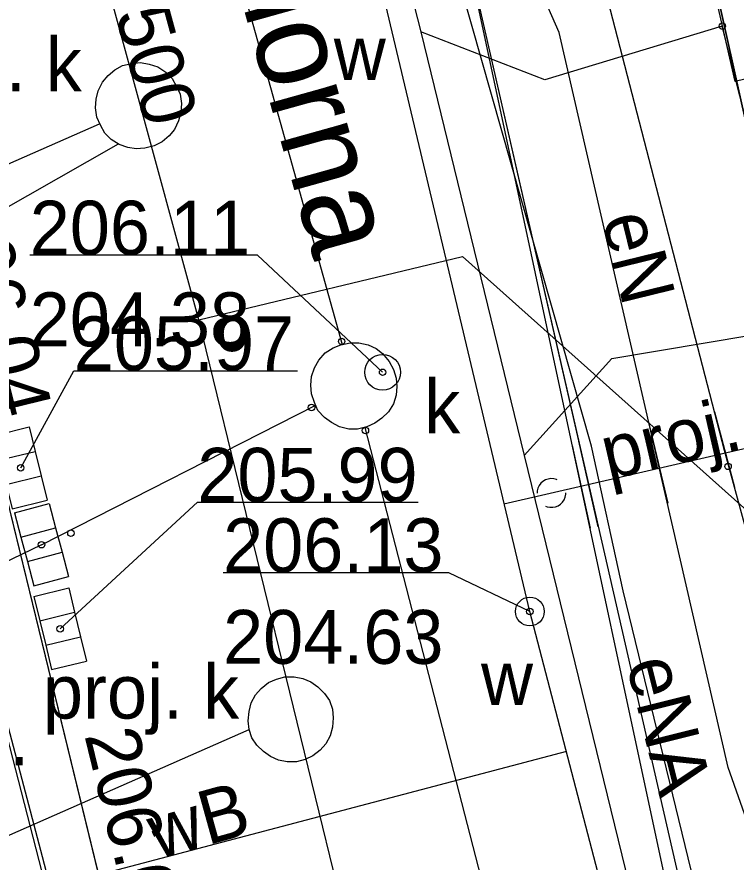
# Model space of a CAD drawing. Extents: x 6512400 to 6513200, y 6022500 to 6022750.
# Drawn here: x 6512855.79 to 6512865.8, y 6022590.23 to 6022602 of the extents above; entities that cross this region are included whole.
import ezdxf

# ---------------------------------------------------------------- set-up
doc = ezdxf.new("R2010")
doc.units = 0
for name, color, linetype in [('217-kontur klasyfikacyjny', 7, 'Continuous'), ('218-kontur użytku gruntowego', 7, 'Continuous'), ('219-działka ewidencyjna', 7, 'Continuous'), ('994-Nazwa ulicy', 7, 'Continuous'), ('budynek projektowany (powierzchnia)', 7, 'Continuous'), ('inna obudowa przewodu - sieć elektroenergetyczna (linia)', 7, 'Continuous'), ('jezdnia', 7, 'Continuous'), ('jezdnia (powierzchnia)', 7, 'Continuous'), ('jezdnia-Atr17', 7, 'Continuous'), ('komora podziemna - przewód kanalizacyjny (powierzchnia)', 7, 'Continuous'), ('kratka ściekowa', 7, 'Continuous'), ('krawężnik', 7, 'Continuous'), ('krawężnik (linia)', 7, 'Continuous'), ('obudowa przewodu projektowana lub w budowie (sieć elektroenergetyczna) - ob. projektowany', 7, 'Continuous'), ('obudowa przewodu projektowana lub w budowie (sieć gazowa) - ob. projektowany', 7, 'Continuous'), ('ogrodzenie trwałe (powierzchnia)', 7, 'Continuous'), ('pikieta sztuczna-Atr2', 7, 'Continuous'), ('przewód elektroenergetyczny (linia)', 7, 'Continuous'), ('przewód elektroenergetyczny (linia)-Atr1', 7, 'Continuous'), ('przewód gazowy (linia)', 7, 'Continuous'), ('przewód kanalizacyjny (linia)', 7, 'Continuous'), ('przewód kanalizacyjny (linia)-Atr1', 7, 'Continuous'), ('przewód kanalizacyjny - projektowany lub w budowie (linia) - ob. projektowany', 7, 'Continuous'), ('przewód wodociągowy (linia)', 7, 'Continuous'), ('przewód wodociągowy (linia)-Atr1', 7, 'Continuous'), ('przewód wodociągowy - projektowany lub w budowie (linia) - ob. projektowany', 7, 'Continuous'), ('przewód wodociągowy - projektowany lub w budowie (linia) - ob. projektowany-Atr1', 7, 'Continuous'), ('punkt o określonej wysokości (sieć gazowa)', 7, 'Continuous'), ('punkt o określonej wysokości (sieć kanalizacyjna)', 7, 'Continuous'), ('punkt o określonej wysokości (sieć kanalizacyjna)-Atr2', 7, 'Continuous'), ('punkt o określonej wysokości (sieć kanalizacyjna)-Atr3', 7, 'Continuous'), ('punkt o określonej wysokości (sieć wodociągowa)', 7, 'Continuous'), ('punkt o określonej wysokości (sieć wodociągowa)-Atr2', 7, 'Continuous'), ('punkt o określonej wysokości (sieć wodociągowa)-Atr3', 7, 'Continuous'), ('punkt wysokościowy naturalny', 7, 'Continuous'), ('rzedna', 7, 'Continuous'), ('rzedna-Atr2', 7, 'Continuous'), ('urządzenie techniczne projektowane lub w budowie (sieć kanalizacyjna) - powierzchnia - ob. projektowany', 7, 'Continuous'), ('urządzenie techniczne projektowane lub w budowie (sieć kanalizacyjna) - powierzchnia - ob. projektowany-Atr17', 7, 'Continuous'), ('urządzenie techniczne projektowane lub w budowie (sieć wodociągowa) - punkt - ob. projektowany', 7, 'Continuous'), ('właz okrągły - siec kanalizacyjna (punkt)', 7, 'Continuous'), ('właz okrągły - siec kanalizacyjna (punkt)-Atr17', 7, 'Continuous'), ('zasuwa - siec wodociągowa (punkt)', 7, 'Continuous'), ('zasuwa - siec wodociągowa (punkt)-Atr17', 7, 'Continuous')]:
    doc.layers.add(name, color=color, linetype=linetype)

# ---------------------------------------------------------------- blocks, each defined once
blk = doc.blocks.new('PW01')
blk.add_circle((0, 0), 0.045)
blk = doc.blocks.new('US22')
blk.add_circle((0, 0), 0.25)
blk = doc.blocks.new('US25')
blk.add_circle((0, 0), 0.2)
blk = doc.blocks.new('US01P')
for points in [[(0.082, 0.181), (0.072, 0.186), (0.034, 0.197), (-0.006, 0.2), (-0.046, 0.194), (-0.084, 0.182), (-0.118, 0.161), (-0.148, 0.135), (-0.172, 0.103), (-0.189, 0.066), (-0.198, 0.028), (-0.2, -0.001)], [(-0.082, -0.182), (-0.061, -0.191), (-0.022, -0.199), (0.018, -0.199), (0.057, -0.192), (0.094, -0.177), (0.127, -0.155), (0.155, -0.126), (0.177, -0.093), (0.192, -0.056), (0.199, -0.016), (0.2, 0)]]:
    blk.add_lwpolyline(points)
blk = doc.blocks.new('US05')
for p, q in [((-0.525, -0.25), (-0.525, 0.25)), ((-0.525, 0.25), (-0.175, 0.25)), ((-0.175, -0.25), (-0.175, 0.25)), ((-0.175, 0.25), (0.175, 0.25)), ((0.175, -0.25), (0.175, 0.25)), ((0.175, 0.25), (0.525, 0.25)), ((0.525, -0.25), (0.525, 0.25)), ((-0.525, -0.25), (-0.175, -0.25)), ((-0.175, -0.25), (0.175, -0.25)), ((0.175, -0.25), (0.525, -0.25))]:
    blk.add_line(p, q)

msp = doc.modelspace()

# ---------------------------------------------------------------- linework, layer by layer
at = {"layer": '217-kontur klasyfikacyjny'}
msp.add_lwpolyline([(6512862.63, 6022615.38), (6512866.69, 6022597.16)], dxfattribs=at)
at = {"layer": '218-kontur użytku gruntowego'}
for points in [[(6512862.63, 6022615.38), (6512866.69, 6022597.16)], [(6512866.69, 6022597.16), (6512862.63, 6022615.38)]]:
    msp.add_lwpolyline(points, dxfattribs=at)
at = {"layer": '219-działka ewidencyjna'}
msp.add_lwpolyline([(6512866.69, 6022597.16), (6512862.63, 6022615.38)], dxfattribs=at)
at = {"layer": 'budynek projektowany (powierzchnia)'}
msp.add_lwpolyline([(6512876.905, 6022604.629), (6512866.3, 6022602.19), (6512866.5, 6022601.27), (6512865.79, 6022601.1), (6512863.94, 6022609.18), (6512865.92, 6022609.63), (6512865.01, 6022613.81), (6512862.96, 6022613.3), (6512860.72, 6022623.09)], dxfattribs=at)
at = {"layer": 'inna obudowa przewodu - sieć elektroenergetyczna (linia)'}
msp.add_lwpolyline([(6512862.37, 6022601.52), (6512863.69, 6022595.73)], dxfattribs=at)
at = {"layer": 'jezdnia'}
msp.add_lwpolyline([(6512857.23, 6022588.82), (6512855.05, 6022597.75), (6512854.94, 6022596.77), (6512854.71, 6022596.06), (6512854.24, 6022595.41), (6512853.71, 6022594.99), (6512853.21, 6022594.73), (6512852.17, 6022594.41), (6512852.27, 6022594.15), (6512853.67, 6022590.44), (6512853.87, 6022590.02), (6512854.31, 6022590.11), (6512855.01, 6022590.11), (6512855.7, 6022590.01), (6512856.23, 6022589.8), (6512856.78, 6022589.31)], close=True, dxfattribs=at)
at = {"layer": 'jezdnia (powierzchnia)'}
msp.add_lwpolyline([(6512861.41, 6022601.79), (6512862.85, 6022595.89), (6512864.07, 6022597.24), (6512866.67, 6022597.68), (6512865.61, 6022601.87), (6512863.14, 6022601.12)], close=True, dxfattribs=at)
at = {"layer": 'komora podziemna - przewód kanalizacyjny (powierzchnia)'}
msp.add_lwpolyline([(6512861.08, 6022596.85), (6512861.07, 6022596.73), (6512861.03, 6022596.61), (6512860.96, 6022596.5), (6512860.87, 6022596.41), (6512860.77, 6022596.34), (6512860.66, 6022596.29), (6512860.53, 6022596.26), (6512860.41, 6022596.26), (6512860.28, 6022596.29), (6512860.17, 6022596.35), (6512860.07, 6022596.42), (6512859.98, 6022596.52), (6512859.93, 6022596.63), (6512859.89, 6022596.75), (6512859.88, 6022596.87), (6512859.89, 6022596.99), (6512859.93, 6022597.11), (6512859.99, 6022597.22), (6512860.08, 6022597.32), (6512860.19, 6022597.39), (6512860.3, 6022597.43), (6512860.43, 6022597.46), (6512860.55, 6022597.46), (6512860.68, 6022597.43), (6512860.79, 6022597.38), (6512860.88, 6022597.31), (6512860.97, 6022597.2), (6512861.03, 6022597.09), (6512861.07, 6022596.97)], close=True, dxfattribs=at)
at = {"layer": 'krawężnik'}
msp.add_lwpolyline([(6512857.23, 6022588.82), (6512855.05, 6022597.75), (6512854.94, 6022596.77), (6512854.71, 6022596.06), (6512854.24, 6022595.41), (6512853.71, 6022594.99), (6512853.21, 6022594.73), (6512852.17, 6022594.41), (6512852.27, 6022594.15), (6512853.67, 6022590.44), (6512853.87, 6022590.02), (6512854.31, 6022590.11), (6512855.01, 6022590.11), (6512855.7, 6022590.01), (6512856.23, 6022589.8), (6512856.78, 6022589.31)], close=True, dxfattribs=at)
at = {"layer": 'krawężnik (linia)'}
for points in [[(6512859.76, 6022608.23), (6512861.41, 6022601.79)], [(6512858.01, 6022586.22), (6512857.23, 6022588.81), (6512855.05, 6022597.75), (6512854.71, 6022599.38), (6512853.35, 6022605.1)], [(6512862.85, 6022595.89), (6512865.97, 6022583.13), (6512868.17, 6022574.3)]]:
    msp.add_lwpolyline(points, dxfattribs=at)
at = {"layer": 'obudowa przewodu projektowana lub w budowie (sieć elektroenergetyczna) - ob. projektowany'}
for points in [[(6512864.6, 6022596.28), (6512864.85, 6022595.23)], [(6512863.88, 6022594.9), (6512863.61, 6022596.09)], [(6512863.52, 6022596.03), (6512863.77, 6022594.88)]]:
    msp.add_lwpolyline(points, dxfattribs=at)
at = {"layer": 'obudowa przewodu projektowana lub w budowie (sieć gazowa) - ob. projektowany'}
msp.add_lwpolyline([(6512865.5, 6022596.5), (6512865.78, 6022595.45)], dxfattribs=at)
at = {"layer": 'ogrodzenie trwałe (powierzchnia)'}
msp.add_lwpolyline([(6512866.67, 6022597.68), (6512865.61, 6022601.87)], dxfattribs=at)
at = {"layer": 'przewód elektroenergetyczny (linia)'}
for points in [[(6512763.38, 6022676.06), (6512798.79, 6022676.04), (6512803.06, 6022673.02), (6512807.84, 6022668.96), (6512815.24, 6022662.53), (6512819.98, 6022657.77), (6512831.6, 6022645.79), (6512834.59, 6022642.25), (6512837.06, 6022638.75), (6512840.02, 6022634.13), (6512842.26, 6022630.04), (6512846.03, 6022621.35), (6512846.58, 6022618.9), (6512847.6, 6022616.23), (6512852.12, 6022605.09), (6512853.39, 6022601.13), (6512855.57, 6022592.48), (6512858.1, 6022582.86), (6512868.09, 6022584.49), (6512870.03, 6022584.23), (6512871.36, 6022584.34), (6512875.65, 6022585.56), (6512879.74, 6022586.61), (6512881.754, 6022587.357)], [(6512802.27, 6022673.66), (6512807.42, 6022670.09), (6512811.38, 6022666.87), (6512814.66, 6022663.43), (6512826.4, 6022651.65), (6512827.82, 6022650.09), (6512834.03, 6022642.46), (6512842.84, 6022631.19), (6512844.67, 6022626.95), (6512847.57, 6022619.87), (6512849.81, 6022612.67), (6512853.56, 6022600.08), (6512856.46, 6022588.83), (6512861.26, 6022569.82), (6512861.768, 6022567.654)], [(6512861.56, 6022603.29), (6512861.94, 6022603.39), (6512866.18, 6022583.61), (6512856.81, 6022581.85), (6512858.91, 6022573.95), (6512860.571, 6022567.194)], [(6512861.56, 6022603.29), (6512861.94, 6022603.39), (6512866.36, 6022584.08), (6512868.34, 6022583.06), (6512881.4, 6022587.22)], [(6512869.91, 6022577.24), (6512869.61, 6022577.28), (6512867.83, 6022585.48), (6512865.69, 6022591.55), (6512863.34, 6022601.78), (6512862.79, 6022603.03), (6512861.56, 6022603.29)]]:
    msp.add_lwpolyline(points, dxfattribs=at)
at = {"layer": 'przewód gazowy (linia)'}
msp.add_lwpolyline([(6512871.862, 6022571.535), (6512870.29, 6022578.43), (6512869.58, 6022581.52), (6512865.64, 6022595.96), (6512860.06, 6022617.51), (6512858.39, 6022625.33), (6512855.49, 6022634.19), (6512854.83, 6022641.62)], dxfattribs=at)
at = {"layer": 'przewód kanalizacyjny (linia)'}
for points in [[(6512860.32, 6022597.43), (6512854.34, 6022618.87)], [(6512861.16, 6022586.16), (6512858.32, 6022597.78), (6512853.7, 6022614.72)], [(6512858.32, 6022597.78), (6512861.99, 6022598.66)], [(6512861.99, 6022598.66), (6512867.39, 6022593.84)], [(6512856.13, 6022594.65), (6512859.94, 6022596.59)], [(6512860.63, 6022596.28), (6512867.451, 6022569.839)]]:
    msp.add_lwpolyline(points, dxfattribs=at)
at = {"layer": 'przewód kanalizacyjny - projektowany lub w budowie (linia) - ob. projektowany'}
for points in [[(6512849.73, 6022597.34), (6512856.94, 6022600.51)], [(6512851.27, 6022593.61), (6512852.18, 6022597.37), (6512857.2, 6022600.23)], [(6512853.09, 6022589.47), (6512859.02, 6022592.08)]]:
    msp.add_lwpolyline(points, dxfattribs=at)
at = {"layer": 'przewód wodociągowy (linia)'}
for points in [[(6512869.887, 6022570.776), (6512864.23, 6022594.01), (6512863.79, 6022596.02), (6512861.84, 6022602.88)], [(6512862.93, 6022593.72), (6512860.86, 6022602.44)], [(6512869.005, 6022570.437), (6512862.93, 6022593.72)], [(6512863.44, 6022591.77), (6512853.83, 6022589.24)]]:
    msp.add_lwpolyline(points, dxfattribs=at)
at = {"layer": 'przewód wodociągowy - projektowany lub w budowie (linia) - ob. projektowany'}
msp.add_lwpolyline([(6512862.57, 6022595.22), (6512871.22, 6022597.21), (6512871.56, 6022595.75)], dxfattribs=at)
at = {"layer": 'punkt o określonej wysokości (sieć kanalizacyjna)-Atr2'}
for points in [[(6512860.88, 6022597.05), (6512859.14, 6022598.68), (6512855.967, 6022598.68)], [(6512856.13, 6022594.65), (6512852.57, 6022592.93), (6512849.429, 6022592.93)]]:
    msp.add_lwpolyline(points, dxfattribs=at)
at = {"layer": 'punkt o określonej wysokości (sieć wodociągowa)-Atr2'}
msp.add_lwpolyline([(6512862.93, 6022593.72), (6512861.8, 6022594.26), (6512858.659, 6022594.26)], dxfattribs=at)
at = {"layer": 'rzedna-Atr2'}
for points in [[(6512855.84, 6022595.72), (6512856.58, 6022597.07), (6512859.694, 6022597.07)], [(6512856.39, 6022593.48), (6512858.3, 6022595.24), (6512861.377, 6022595.24)]]:
    msp.add_lwpolyline(points, dxfattribs=at)
at = {"layer": 'urządzenie techniczne projektowane lub w budowie (sieć kanalizacyjna) - powierzchnia - ob. projektowany'}
for points in [[(6512857.91, 6022600.34), (6512857.81, 6022600.26), (6512857.7, 6022600.2), (6512857.57, 6022600.17), (6512857.45, 6022600.16), (6512857.33, 6022600.18), (6512857.21, 6022600.22), (6512857.1, 6022600.29), (6512857.01, 6022600.38), (6512856.95, 6022600.49), (6512856.9, 6022600.6), (6512856.88, 6022600.73), (6512856.89, 6022600.85), (6512856.92, 6022600.97), (6512856.98, 6022601.09), (6512857.06, 6022601.18), (6512857.15, 6022601.26), (6512857.26, 6022601.32), (6512857.39, 6022601.35), (6512857.51, 6022601.36), (6512857.63, 6022601.34), (6512857.75, 6022601.3), (6512857.86, 6022601.23), (6512857.95, 6022601.14), (6512858.01, 6022601.03), (6512858.06, 6022600.92), (6512858.08, 6022600.79), (6512858.07, 6022600.67), (6512858.04, 6022600.55), (6512857.98, 6022600.43)], [(6512860.15, 6022591.99), (6512860.09, 6022591.88), (6512860.01, 6022591.79), (6512859.91, 6022591.71), (6512859.8, 6022591.66), (6512859.68, 6022591.63), (6512859.55, 6022591.63), (6512859.43, 6022591.65), (6512859.32, 6022591.7), (6512859.22, 6022591.77), (6512859.13, 6022591.86), (6512859.06, 6022591.96), (6512859.02, 6022592.08), (6512859.01, 6022592.2), (6512859.02, 6022592.33), (6512859.05, 6022592.45), (6512859.11, 6022592.56), (6512859.19, 6022592.65), (6512859.29, 6022592.73), (6512859.4, 6022592.78), (6512859.52, 6022592.81), (6512859.65, 6022592.81), (6512859.77, 6022592.79), (6512859.88, 6022592.74), (6512859.98, 6022592.67), (6512860.07, 6022592.58), (6512860.14, 6022592.48), (6512860.18, 6022592.36), (6512860.19, 6022592.24), (6512860.18, 6022592.11)]]:
    msp.add_lwpolyline(points, close=True, dxfattribs=at)

# ---------------------------------------------------------------- block references
at = {"layer": 'kratka ściekowa'}
for p, rotation in [((6512855.84, 6022595.72), -76.201), ((6512856.13, 6022594.65), -75.203), ((6512856.39, 6022593.48), -76.39900000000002)]:
    msp.add_blockref('US05', p, dxfattribs=dict(at, rotation=rotation))
at = {"layer": 'punkt o określonej wysokości (sieć gazowa)'}
msp.add_blockref('PW01', (6512865.69, 6022595.74), dxfattribs=at)
at = {"layer": 'punkt o określonej wysokości (sieć kanalizacyjna)'}
for p, rotation in [((6512860.31, 6022597.48), -73.609), ((6512859.89, 6022596.56), 28.412), ((6512860.64, 6022596.24), -74.738), ((6512856.54, 6022594.81), 28.412), ((6512856.13, 6022594.65), -75.256)]:
    msp.add_blockref('PW01', p, dxfattribs=dict(at, rotation=rotation))
msp.add_blockref('PW01', (6512860.88, 6022597.05), dxfattribs=at)
at = {"layer": 'punkt o określonej wysokości (sieć wodociągowa)', "rotation": -74.589}
msp.add_blockref('PW01', (6512862.93, 6022593.72), dxfattribs=at)
at = {"layer": 'punkt wysokościowy naturalny'}
msp.add_blockref('PW01', (6512865.61, 6022601.87), dxfattribs=at)
at = {"layer": 'rzedna'}
for p in [(6512855.84, 6022595.72), (6512856.39, 6022593.48)]:
    msp.add_blockref('PW01', p, dxfattribs=at)
at = {"layer": 'urządzenie techniczne projektowane lub w budowie (sieć wodociągowa) - punkt - ob. projektowany'}
msp.add_blockref('US01P', (6512863.23, 6022595.37), dxfattribs=at)
at = {"layer": 'właz okrągły - siec kanalizacyjna (punkt)'}
msp.add_blockref('US22', (6512860.88, 6022597.05), dxfattribs=at)
at = {"layer": 'zasuwa - siec wodociągowa (punkt)', "rotation": -74.589}
msp.add_blockref('US25', (6512862.93, 6022593.72), dxfattribs=at)

# ---------------------------------------------------------------- texts
at = {"layer": '994-Nazwa ulicy'}
msp.add_text('Jeziorna', height=1.25, rotation=285.602, dxfattribs=at).set_placement((6512858.23, 6022604.67))
at = {"layer": 'jezdnia-Atr17'}
msp.add_text('j.kb.', height=0.75, dxfattribs=at).set_placement((6512854.12, 6022591.58))
at = {"layer": 'pikieta sztuczna-Atr2'}
for s, p in [('206.04', (6512854.83, 6022599.361)), ('206.06', (6512856.725, 6022592.001))]:
    msp.add_text(s, height=0.75, rotation=283.719, dxfattribs=at).set_placement(p)
at = {"layer": 'przewód elektroenergetyczny (linia)-Atr1'}
for s, rotation, p in [('eN', 283.771, (6512863.93, 6022599.19)), ('eNA', 283.986, (6512864.27, 6022593))]:
    msp.add_text(s, height=0.75, rotation=rotation, dxfattribs=at).set_placement(p)
at = {"layer": 'przewód kanalizacyjny (linia)-Atr1'}
msp.add_text('ks500', height=0.75, rotation=285.255, dxfattribs=at).set_placement((6512856.89, 6022603.01))
at = {"layer": 'przewód wodociągowy (linia)-Atr1'}
msp.add_text('wB', height=0.75, rotation=15.533, dxfattribs=at).set_placement((6512857.74, 6022590.27))
at = {"layer": 'przewód wodociągowy - projektowany lub w budowie (linia) - ob. projektowany-Atr1'}
msp.add_text('proj. w', height=0.75, rotation=12.956, dxfattribs=at).set_placement((6512864.02, 6022595.55))
at = {"layer": 'punkt o określonej wysokości (sieć kanalizacyjna)-Atr2'}
msp.add_text('206.11', height=0.75, dxfattribs=at).set_placement((6512855.967, 6022598.688))
at = {"layer": 'punkt o określonej wysokości (sieć kanalizacyjna)-Atr3'}
msp.add_text('204.38', height=0.75, dxfattribs=at).set_placement((6512855.967, 6022597.412))
at = {"layer": 'punkt o określonej wysokości (sieć wodociągowa)-Atr2'}
msp.add_text('206.13', height=0.75, dxfattribs=at).set_placement((6512858.659, 6022594.268))
at = {"layer": 'punkt o określonej wysokości (sieć wodociągowa)-Atr3'}
msp.add_text('204.63', height=0.75, dxfattribs=at).set_placement((6512858.659, 6022592.992))
at = {"layer": 'rzedna-Atr2'}
for s, p in [('205.97', (6512856.58, 6022597.078)), ('205.99', (6512858.3, 6022595.248))]:
    msp.add_text(s, height=0.75, dxfattribs=at).set_placement(p)
at = {"layer": 'urządzenie techniczne projektowane lub w budowie (sieć kanalizacyjna) - powierzchnia - ob. projektowany-Atr17'}
for p in [(6512853.96, 6022600.96), (6512856.15, 6022592.23)]:
    msp.add_text('proj. k', height=0.75, dxfattribs=at).set_placement(p)
at = {"layer": 'właz okrągły - siec kanalizacyjna (punkt)-Atr17'}
msp.add_text('k', height=0.75, dxfattribs=at).set_placement((6512861.46, 6022596.2))
at = {"layer": 'zasuwa - siec wodociągowa (punkt)-Atr17'}
for p in [(6512860.2, 6022601.12), (6512862.25, 6022592.42)]:
    msp.add_text('w', height=0.75, dxfattribs=at).set_placement(p)

doc.saveas('drawing.dxf')
